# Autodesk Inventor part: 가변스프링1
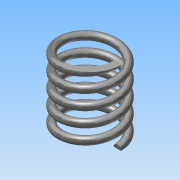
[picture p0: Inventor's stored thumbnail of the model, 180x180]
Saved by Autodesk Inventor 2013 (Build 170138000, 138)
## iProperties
Created: 2015-02
Part Number: 가변스프링1
Material: 강철, 탄소
Document SubType Name: Modeling
Designer: WINDOWS7
Density: 7.87 g/cm^3
Mass: 18.9518 g
Surface Area: 32.5528 cm^2
Volume: 2.40811 cm^3
Author: WINDOWS7
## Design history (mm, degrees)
sketch "스케치1"
  geometry: L1 (0, 0)-(11, 0); L2 (11, 0)-(11, 40.095); L3 (11, 40.095)-(0, 40.095); L4 (0, 40.095)-(0, 0); C1 r 1.5 at (11, 0)
  constraints: 8 end point, 2 parallel, 1 centre point, 1 coincident, 1 horizontal, 1 perpendicular
  dimensions: "d0" = 3 diameter of C1; "d2" = 22 diameter of L2 L4; "d3" = 40.0955 distance between parallel lines of L1 L3 (derived)
feature "코일1" sketch "스케치1" pitch "d4" = 10; turns "d6" = 5; dims "d5" = 40.0955 (= d3), "d7" = 0, angle "d8" = 90 deg, angle "d9" = 90 deg, "d10" = 0, "d11" = 0
feature "분할1"
node "작업 평면1"
feature "분할2"
node "솔리드1"
other parameters: "d12" = 90 deg
